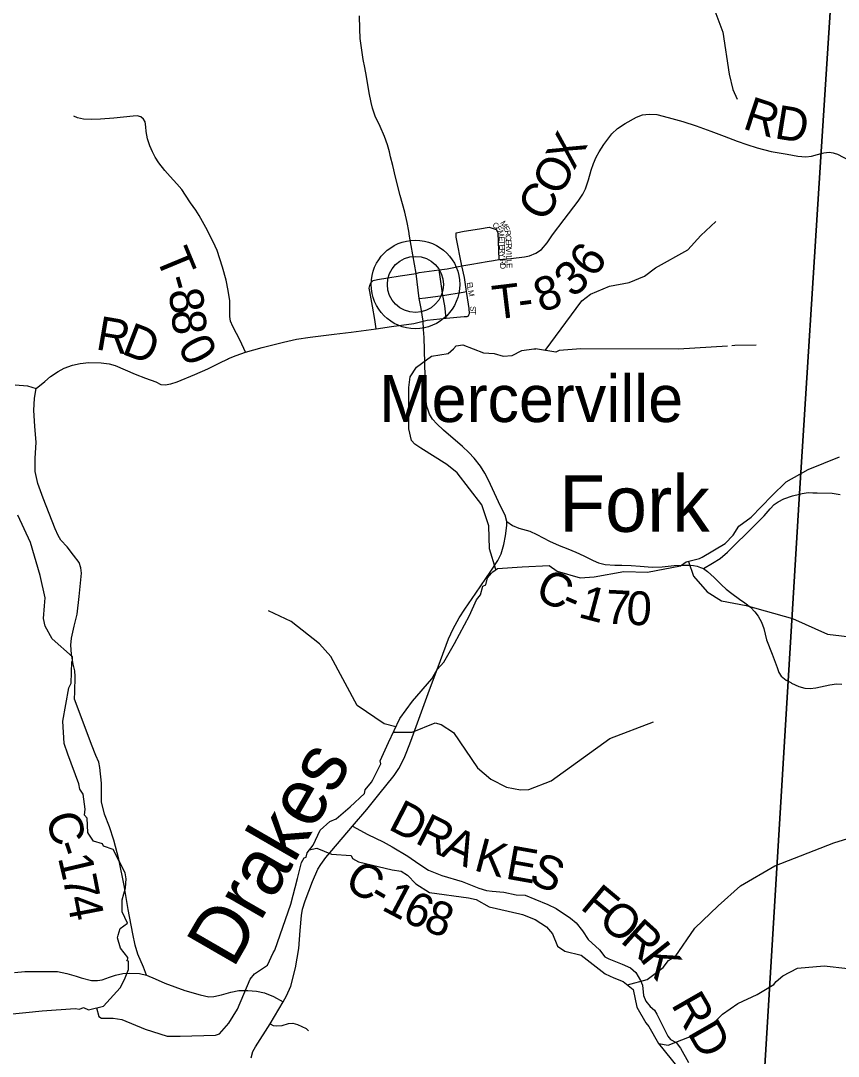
# Model space of a CAD drawing. Extents: x -1.8 to 75.7, y -2 to 25.
# Drawn here: x 4.882 to 6.256, y 15.242 to 16.983 of the extents above; entities that cross this region are included whole.
import ezdxf

# ---------------------------------------------------------------- set-up
doc = ezdxf.new("R2010")
doc.units = 0
for name, color, linetype in [('GM_X_County_Road', 7, 'Continuous'), ('GM_X_County_Road_Text', 7, 'Continuous'), ('GM_X_Minor_River', 7, 'Continuous'), ('GM_X_Minor_River_Text', 7, 'Continuous'), ('GM_X_State_Route', 7, 'Continuous'), ('GM_X_Township', 7, 'Continuous'), ('GM_X_Township_Road', 7, 'Continuous'), ('GM_X_Township_Road_Text', 7, 'Continuous'), ('GM_X_Township_Subdivision', 7, 'Continuous'), ('GM_X_Township_Subdivision_Text', 7, 'Continuous'), ('GM_X_Unincorporated', 7, 'Continuous'), ('GM_X_Unincorporated_Location', 7, 'Continuous'), ('GM_X_Unincorporated_Text', 7, 'Continuous')]:
    doc.layers.add(name, color=color, linetype=linetype)

msp = doc.modelspace()

# ---------------------------------------------------------------- linework, layer by layer
at = {"layer": 'GM_X_County_Road'}
for points in [[(5.2313, 16.415), (5.2438, 16.42), (5.2594, 16.4259), (5.2874, 16.4337), (5.3234, 16.4427), (5.3451, 16.4474), (5.3684, 16.4508), (5.4086, 16.4558), (5.4371, 16.4593), (5.479, 16.4652), (5.5047, 16.4687), (5.5422, 16.4737), (5.558, 16.4776)], [(4.8724, 16.3711), (4.8936, 16.369), (4.908, 16.3647), (4.9225, 16.3766), (4.9322, 16.3848), (4.9446, 16.3934), (4.9551, 16.3988), (4.9692, 16.4039), (4.9818, 16.4069), (4.9966, 16.4086), (5.0172, 16.4077), (5.0307, 16.406), (5.0407, 16.4032), (5.0574, 16.3962), (5.0741, 16.3889), (5.0915, 16.382), (5.1088, 16.3756), (5.1174, 16.3713), (5.1249, 16.3709), (5.1341, 16.3724), (5.1446, 16.3758), (5.1742, 16.388), (5.1964, 16.3979), (5.2166, 16.408), (5.2292, 16.4142), (5.2313, 16.415)], [(5.0934, 15.3788), (5.0881, 15.3921), (5.0786, 15.4141), (5.0742, 15.4291), (5.0705, 15.448), (5.0626, 15.4889), (5.0555, 15.5292), (5.0467, 15.5736), (5.0386, 15.6057), (5.0309, 15.6282), (5.0228, 15.649), (5.0177, 15.6697), (5.0175, 15.7014), (5.0151, 15.7276), (5.0131, 15.7368), (5.0082, 15.7478), (5.0006, 15.7661), (4.9819, 15.8171), (4.9724, 15.8426), (4.9728, 15.855), (4.9733, 15.8807), (4.9731, 15.8904), (4.9698, 15.9014), (4.9671, 15.9179), (4.9662, 15.933), (4.9673, 15.9451), (4.9717, 15.9652), (4.977, 15.9854), (4.9799, 16.0151), (4.9838, 16.0543), (4.9832, 16.0633), (4.9799, 16.0723), (4.9709, 16.0848), (4.9601, 16.0983), (4.9491, 16.1099), (4.9447, 16.1178), (4.9401, 16.1286), (4.9198, 16.1803), (4.9108, 16.2049), (4.9064, 16.225), (4.9064, 16.2478), (4.9079, 16.2738), (4.9057, 16.3013), (4.9038, 16.3275), (4.9049, 16.3482), (4.908, 16.3647)], [(5.6988, 16.1413), (5.7084, 16.1346), (5.7189, 16.1301), (5.7372, 16.1247), (5.7489, 16.1193), (5.7706, 16.1078), (5.7864, 16.1006), (5.8009, 16.0951), (5.8146, 16.0895), (5.8279, 16.0836), (5.8435, 16.0755), (5.8526, 16.0718), (5.8637, 16.0691), (5.8802, 16.068), (5.8921, 16.068), (5.9073, 16.0673), (5.9229, 16.0658), (5.943, 16.0646), (5.9594, 16.0651), (5.98, 16.0669), (5.9943, 16.0678), (6.0042, 16.0678), (6.0123, 16.0669), (6.0184, 16.0658), (6.024, 16.064), (6.029, 16.0622), (6.0358, 16.0569), (6.0471, 16.0468), (6.0593, 16.0348), (6.067, 16.0276), (6.0767, 16.0201), (6.0893, 16.0106), (6.0986, 16.0046), (6.1079, 15.9973), (6.1155, 15.9894), (6.121, 15.9822), (6.1268, 15.972), (6.1307, 15.9614), (6.1352, 15.9424), (6.1443, 15.9183), (6.1526, 15.8956), (6.1558, 15.8871), (6.1598, 15.8814), (6.1679, 15.8747), (6.1712, 15.8728), (6.1756, 15.8703)], [(6.1756, 15.8703), (6.1772, 15.8694), (6.189, 15.8638), (6.1994, 15.8609), (6.2084, 15.8606), (6.2179, 15.8618), (6.2416, 15.8668), (6.2525, 15.8683), (6.2615, 15.8676)], [(5.4393, 15.6292), (5.4649, 15.615), (5.4908, 15.6025), (5.5059, 15.5945), (5.5323, 15.5784), (5.5509, 15.5659), (5.5671, 15.5553), (5.5893, 15.5463), (5.6236, 15.5361), (5.6517, 15.5249), (5.6643, 15.5209), (5.6743, 15.5199), (5.6939, 15.518), (5.7144, 15.5139), (5.7292, 15.5131), (5.7459, 15.5063), (5.7673, 15.4972), (5.7814, 15.4905), (5.8059, 15.4742), (5.8154, 15.4668), (5.826, 15.4529), (5.8351, 15.4387), (5.8543, 15.421), (5.8633, 15.4097), (5.8702, 15.406), (5.8926, 15.3971), (5.9063, 15.3907), (5.9152, 15.3831), (5.9232, 15.3698), (5.9266, 15.3618), (5.9285, 15.3443), (5.9321, 15.3347), (5.9393, 15.3261), (5.9467, 15.3197), (5.9507, 15.3132), (5.9629, 15.2883), (5.9693, 15.276), (5.9737, 15.2707), (5.983, 15.2654), (5.9902, 15.2557), (6.0037, 15.232)], [(4.8716, 15.3832), (4.8889, 15.3845), (4.9276, 15.3845), (4.9437, 15.3845), (4.9595, 15.3812), (4.975, 15.3768), (4.9835, 15.3742), (5.0008, 15.3694), (5.0108, 15.3694), (5.0189, 15.3705), (5.0312, 15.3751), (5.041, 15.3786), (5.0534, 15.3814), (5.065, 15.3821), (5.0814, 15.3812), (5.0934, 15.3788), (5.1079, 15.3727), (5.1238, 15.3653), (5.1577, 15.353), (5.1837, 15.3454), (5.1979, 15.3421), (5.2064, 15.3425), (5.2193, 15.3456), (5.2348, 15.3502), (5.2486, 15.3526), (5.2633, 15.3528), (5.2783, 15.3515), (5.2914, 15.3489), (5.3067, 15.343), (5.3229, 15.334)]]:
    msp.add_lwpolyline(points, dxfattribs=at)
at = {"layer": 'GM_X_Minor_River'}
for points in [[(5.9283, 17.1384), (5.9903, 17.1035), (6.0164, 17.0554), (6.0416, 17.0172), (6.0617, 16.9637), (6.072, 16.8928), (6.0782, 16.867), (6.0859, 16.8507)], [(5.7632, 16.4287), (5.8245, 16.5122), (5.8392, 16.5232), (5.8713, 16.5365), (5.9044, 16.5431), (5.9297, 16.5537), (5.9482, 16.5675), (6.0025, 16.598), (6.0247, 16.6216), (6.0496, 16.6455)], [(5.6804, 16.0603), (5.6693, 16.095), (5.6686, 16.1341), (5.6564, 16.169), (5.615, 16.2228), (5.598, 16.237), (5.5542, 16.2642), (5.5439, 16.271), (5.5384, 16.2772), (5.5341, 16.2971), (5.5343, 16.3662), (5.536, 16.384), (5.547, 16.4003), (5.5722, 16.4189), (5.5999, 16.4237), (5.6088, 16.4314), (5.6135, 16.4362), (5.6249, 16.4381), (5.6593, 16.4245), (5.6774, 16.4235), (5.6927, 16.4189), (5.7079, 16.4199), (5.7237, 16.4285), (5.7442, 16.4316), (5.7472, 16.4315)], [(6.0696, 16.436), (5.9872, 16.4307), (5.8232, 16.4314), (5.7864, 16.4288), (5.781, 16.4255), (5.7468, 16.4315)], [(6.1176, 16.4376), (6.0819, 16.4368), (6.0769, 16.4365)], [(5.0095, 15.3237), (5.0131, 15.3092), (5.0176, 15.3065), (5.0373, 15.3062), (5.052, 15.304), (5.091, 15.2881), (5.128, 15.276), (5.1499, 15.2761), (5.2093, 15.2777), (5.2157, 15.28), (5.2316, 15.2979), (5.2463, 15.3215), (5.2674, 15.3721), (5.275, 15.3809), (5.2965, 15.3954), (5.3063, 15.4163), (5.309, 15.4205), (5.3357, 15.4981), (5.347, 15.541), (5.3538, 15.568), (5.358, 15.5757), (5.3617, 15.5768), (5.3632, 15.584), (5.3731, 15.5973), (5.3848, 15.6225), (5.4014, 15.6369), (5.412, 15.6411), (5.4354, 15.6617), (5.4595, 15.6842), (5.4607, 15.6899), (5.4712, 15.7028), (5.4735, 15.7067), (5.4867, 15.7337), (5.486, 15.739), (5.4999, 15.7694), (5.5188, 15.8101), (5.5403, 15.8394), (5.5724, 15.8768), (5.5818, 15.8924), (5.5928, 15.9049), (5.6105, 15.9361), (5.6362, 15.9829), (5.6479, 16.0096), (5.6543, 16.0176), (5.6584, 16.0324), (5.6634, 16.0347), (5.6664, 16.0465), (5.6728, 16.0541), (5.6751, 16.0564), (5.683, 16.0621), (5.7246, 16.0652), (5.7699, 16.0669), (5.7835, 16.0574), (5.8221, 16.0465), (5.8456, 16.048), (5.8951, 16.0569), (5.9351, 16.0562), (5.9907, 16.0666), (6.0001, 16.0731), (6.0224, 16.0792), (6.027, 16.0811), (6.0655, 16.1044), (6.0787, 16.1181), (6.0885, 16.133), (6.1089, 16.1482), (6.1441, 16.184), (6.1679, 16.2076), (6.2049, 16.2283), (6.2578, 16.25)], [(4.9612, 15.7503), (4.9552, 15.7682), (4.9525, 15.8058), (4.963, 15.8617), (4.9668, 15.8693), (4.9679, 15.905), (4.969, 15.9073), (4.9687, 15.9138), (4.935, 15.9437), (4.9229, 15.965), (4.9202, 15.9779), (4.9221, 15.9992), (4.9228, 16.0128), (4.9149, 16.0501), (4.8985, 16.1059), (4.8773, 16.1515)], [(6.0038, 16.0741), (6.0123, 16.0492), (6.0352, 16.0227), (6.0596, 16.0077), (6.1006, 15.9999), (6.1786, 15.9783), (6.2372, 15.9516), (6.3078, 15.9436), (6.3416, 15.9354), (6.3546, 15.9287), (6.3676, 15.9132), (6.3894, 15.8859), (6.4197, 15.836), (6.4433, 15.8194), (6.457, 15.8141), (6.5031, 15.7817), (6.5138, 15.7765), (6.5369, 15.772), (6.5521, 15.7706), (6.6135, 15.7853)], [(5.5121, 15.7958), (5.4927, 15.8013), (5.447, 15.8318), (5.4028, 15.9143), (5.3837, 15.9355), (5.3365, 15.9732), (5.2984, 15.9909)], [(5.5082, 15.7873), (5.5399, 15.7871), (5.5785, 15.8025), (5.5884, 15.8002), (5.6093, 15.7867), (5.6495, 15.7273), (5.672, 15.708), (5.6979, 15.6945), (5.7219, 15.69), (5.7355, 15.6909), (5.773, 15.7055), (5.8716, 15.7766), (5.9451, 15.8043)], [(4.8573, 15.3123), (4.9178, 15.3185), (4.9734, 15.3228), (4.9805, 15.3213), (4.9877, 15.3243), (4.996, 15.3206), (5.021, 15.3263), (5.0489, 15.3572), (5.0561, 15.3716), (5.0629, 15.3884), (5.0633, 15.402), (5.0602, 15.4028), (5.0621, 15.4062), (5.0617, 15.4081), (5.0496, 15.4241), (5.0447, 15.4411), (5.0458, 15.4457), (5.0492, 15.4571), (5.0613, 15.4659), (5.0526, 15.4853), (5.0522, 15.5054), (5.0582, 15.5255), (5.059, 15.5408), (5.0574, 15.5506), (5.0374, 15.5897), (5.0211, 15.5954), (5.0192, 15.5996), (5.0045, 15.6037), (4.9965, 15.6155), (4.9946, 15.6185), (4.9935, 15.6425), (4.9893, 15.6474), (4.9901, 15.6577), (4.987, 15.6831), (4.981, 15.6911), (4.9798, 15.7002), (4.9612, 15.7503)], [(5.9012, 15.3623), (5.9344, 15.3711), (5.9613, 15.3913), (5.9703, 15.4031), (5.9813, 15.4093), (6.0147, 15.4577), (6.054, 15.4954), (6.0914, 15.529), (6.1488, 15.5624), (6.248, 15.6008), (6.2863, 15.6128), (6.3219, 15.6183)], [(5.3665, 15.5892), (5.3796, 15.592), (5.4039, 15.5821), (5.4371, 15.5795), (5.4396, 15.5749), (5.4493, 15.5693), (5.5062, 15.5557)], [(5.5062, 15.5557), (5.5213, 15.5533), (5.5317, 15.5469), (5.5457, 15.5324), (5.5686, 15.5176), (5.6341, 15.5087), (5.6473, 15.506), (5.6688, 15.4932), (5.7203, 15.4816), (5.7248, 15.4804), (5.7464, 15.4724), (5.7653, 15.4601), (5.7756, 15.448), (5.7836, 15.4276), (5.7959, 15.4192), (5.8236, 15.4123), (5.8639, 15.3806), (5.8784, 15.3741), (5.8941, 15.3679), (5.9107, 15.3548), (5.917, 15.325), (5.9324, 15.2983), (5.9375, 15.2924), (5.9533, 15.2638), (5.9868, 15.2229)], [(5.9536, 15.2635), (5.9698, 15.261), (6.0257, 15.2828), (6.0512, 15.3029), (6.061, 15.3132), (6.0869, 15.331), (6.1195, 15.3462), (6.1472, 15.3628), (6.1511, 15.368), (6.1624, 15.3775), (6.1873, 15.3904), (6.2317, 15.3943), (6.2716, 15.3896)]]:
    msp.add_lwpolyline(points, dxfattribs=at)
at = {"layer": 'GM_X_State_Route'}
for points in [[(5.6916, 16.16), (5.6847, 16.1741), (5.6677, 16.2105), (5.6617, 16.2223), (5.6542, 16.2343), (5.6436, 16.2478), (5.6351, 16.2569), (5.6242, 16.2673), (5.5923, 16.2946), (5.5811, 16.3054), (5.574, 16.3134), (5.5687, 16.3217), (5.5664, 16.3283), (5.5644, 16.3346), (5.5634, 16.3434), (5.5621, 16.3579), (5.5612, 16.384), (5.5605, 16.4294), (5.5596, 16.4505), (5.5589, 16.4638), (5.558, 16.4776), (5.5548, 16.4992), (5.5516, 16.5157), (5.5463, 16.5577), (5.5354, 16.6205), (5.5339, 16.629), (5.5311, 16.6436), (5.5271, 16.6612), (5.5196, 16.6893), (5.5117, 16.72), (5.507, 16.7396), (5.5033, 16.7539), (5.5013, 16.7627), (5.4979, 16.7742), (5.4932, 16.7884), (5.4859, 16.8051), (5.4776, 16.8223), (5.4728, 16.8357), (5.4706, 16.8454), (5.4674, 16.8614), (5.4629, 16.8892), (5.46, 16.9041), (5.4575, 16.9176), (5.4543, 16.9375), (5.4525, 16.9531), (5.4516, 16.9694), (5.4509, 16.9913)], [(5.6824, 16.0738), (5.6835, 16.0756), (5.689, 16.0869), (5.6937, 16.1022), (5.6966, 16.1168), (5.6988, 16.1342), (5.6988, 16.1413), (5.6957, 16.1518), (5.6916, 16.16)], [(5.2692, 15.2398), (5.272, 15.2503), (5.2764, 15.2581), (5.3008, 15.2969), (5.3229, 15.334), (5.3286, 15.3438), (5.3355, 15.3599), (5.3438, 15.391), (5.3491, 15.4235), (5.3516, 15.4539), (5.3535, 15.4789), (5.3554, 15.4896), (5.3596, 15.5033), (5.3721, 15.5359), (5.381, 15.5566), (5.3859, 15.5648), (5.3947, 15.5763), (5.4047, 15.5881), (5.4393, 15.6292), (5.4632, 15.6573), (5.4837, 15.6821), (5.5093, 15.714), (5.5173, 15.7261), (5.5261, 15.7433), (5.5308, 15.7543), (5.5373, 15.7717), (5.5666, 15.8523), (5.5873, 15.9074), (5.6008, 15.944), (5.6087, 15.9608), (5.6188, 15.9792), (5.6282, 15.9936), (5.6466, 16.0204), (5.6716, 16.0574), (5.6824, 16.0738)]]:
    msp.add_lwpolyline(points, dxfattribs=at)
at = {"layer": 'GM_X_Township'}
for points in [[(6.0631, 14.1), (6.0891, 14.525), (6.1136, 14.9242), (6.1259, 15.1242), (6.1707, 15.8638), (6.1898, 16.179), (6.2265, 16.7539), (6.252, 17.1543), (5.4813, 17.1939), (5.2191, 17.2074), (4.6712, 17.2345), (4.4195, 17.2469), (3.6863, 17.2831), (3.1354, 17.3103), (2.1, 17.3659)], [(8.9, 17.0276), (8.8908, 17.028), (8.4894, 17.0481), (7.3049, 17.1072), (7.1962, 17.1121), (6.252, 17.1543), (6.2265, 16.7539), (6.1898, 16.179), (6.1707, 15.8638), (6.1259, 15.1242), (6.1136, 14.9242), (6.0891, 14.525), (6.0631, 14.1)]]:
    msp.add_lwpolyline(points, dxfattribs=at)
at = {"layer": 'GM_X_Township_Road'}
for points in [[(5.2333, 16.4928), (5.2333, 16.497), (5.2333, 16.512), (5.2307, 16.5292), (5.2273, 16.5469), (5.2211, 16.5684), (5.2121, 16.5964), (5.2054, 16.6112), (5.1928, 16.6354), (5.1817, 16.6555), (5.1761, 16.6645), (5.1673, 16.6769), (5.1589, 16.6896), (5.1525, 16.699), (5.1442, 16.7086), (5.1328, 16.7208), (5.1238, 16.7313), (5.114, 16.7442), (5.1078, 16.7534), (5.1031, 16.7622), (5.0988, 16.7725), (5.0949, 16.7844), (5.0928, 16.7964), (5.0921, 16.8044), (5.0911, 16.8127), (5.0883, 16.8176), (5.0836, 16.8215), (5.0776, 16.823), (5.0707, 16.8226), (5.0384, 16.8191), (5.0159, 16.8176), (5.0009, 16.817), (4.9876, 16.8172), (4.9773, 16.8194), (4.9711, 16.8226)], [(5.5851, 16.5642), (5.5986, 16.566), (5.6229, 16.5706), (5.6399, 16.5736), (5.6659, 16.5781), (5.6764, 16.5798), (5.6854, 16.5813), (5.7053, 16.5833), (5.7284, 16.5857), (5.737, 16.5876), (5.7475, 16.5923), (5.7567, 16.5985), (5.7665, 16.6094), (5.7754, 16.6231), (5.7948, 16.6486), (5.8185, 16.6794), (5.8262, 16.6911), (5.8307, 16.7004), (5.8356, 16.7153), (5.8401, 16.7316), (5.8444, 16.7429), (5.8485, 16.7534), (5.8536, 16.7624), (5.8617, 16.775), (5.8752, 16.7926), (5.8844, 16.8014), (5.8973, 16.8103), (5.9163, 16.8208), (5.9268, 16.8247), (5.9377, 16.8257), (5.9505, 16.8251), (5.97, 16.8204), (5.9942, 16.8135), (6.0169, 16.8061), (6.0415, 16.7971), (6.0637, 16.7885), (6.0858, 16.7802), (6.1018, 16.7746), (6.1192, 16.7693), (6.1429, 16.763), (6.1694, 16.7583), (6.1874, 16.7551), (6.2011, 16.7543), (6.2105, 16.7551), (6.2206, 16.7577), (6.2268, 16.7594), (6.2315, 16.7607), (6.2401, 16.7618), (6.2469, 16.7609), (6.2485, 16.7604)], [(6.2485, 16.7604), (6.2544, 16.7588), (6.273, 16.7483), (6.2888, 16.7389), (6.3068, 16.7282), (6.3164, 16.7213), (6.3261, 16.7123), (6.3351, 16.7016), (6.3445, 16.6886), (6.3588, 16.664), (6.3652, 16.6539), (6.3732, 16.6464), (6.3813, 16.6424), (6.3875, 16.6396), (6.3882, 16.6395)], [(5.5463, 16.5577), (5.5514, 16.5595), (5.5851, 16.5642)], [(5.2594, 16.4259), (5.2504, 16.4454), (5.2384, 16.469), (5.2345, 16.4776), (5.2335, 16.4855), (5.2333, 16.4928)], [(6.029, 16.0622), (6.044, 16.0712), (6.0571, 16.0791), (6.0693, 16.0893), (6.0805, 16.101), (6.104, 16.1236), (6.1199, 16.1396), (6.1312, 16.1505), (6.1409, 16.1624), (6.1476, 16.1695), (6.1548, 16.1744), (6.1639, 16.179), (6.1784, 16.1841), (6.1903, 16.1871), (6.1951, 16.1884), (6.205, 16.1896), (6.2126, 16.1895)], [(6.2126, 16.1895), (6.2202, 16.1893), (6.2454, 16.1886), (6.2588, 16.1866)], [(5.3008, 15.2969), (5.3063, 15.294), (5.312, 15.2936), (5.3212, 15.2942), (5.3317, 15.2973), (5.3391, 15.2979), (5.347, 15.2958), (5.3614, 15.289), (5.3653, 15.2851)]]:
    msp.add_lwpolyline(points, dxfattribs=at)
at = {"layer": 'GM_X_Township_Subdivision'}
for points in [[(5.6229, 16.5706), (5.6136, 16.619), (5.6138, 16.6264), (5.6268, 16.6293), (5.6527, 16.6333)], [(5.6527, 16.6333), (5.6691, 16.6358), (5.6805, 16.6319), (5.6836, 16.6264), (5.6854, 16.5813)], [(5.634, 16.487), (5.6351, 16.4886), (5.636, 16.4905), (5.6356, 16.4994), (5.6315, 16.5244), (5.631, 16.5277), (5.6273, 16.5513), (5.6229, 16.5706)], [(5.4739, 16.5461), (5.474, 16.5462), (5.4811, 16.5481), (5.4986, 16.5508), (5.5195, 16.5538), (5.5463, 16.5577)], [(5.5966, 16.4829), (5.5943, 16.5036), (5.5911, 16.5208), (5.5851, 16.5642)], [(5.479, 16.4652), (5.4767, 16.4808), (5.4728, 16.5029), (5.4706, 16.5153), (5.4685, 16.5276), (5.4676, 16.5332), (5.4683, 16.538), (5.4703, 16.5424), (5.4739, 16.5461)], [(5.5516, 16.5157), (5.5623, 16.5171), (5.5911, 16.5208), (5.6255, 16.5267), (5.631, 16.5277)], [(5.558, 16.4776), (5.5647, 16.4795), (5.5966, 16.4829), (5.6268, 16.4856), (5.6323, 16.4859), (5.634, 16.487)]]:
    msp.add_lwpolyline(points, dxfattribs=at)
at = {"layer": 'GM_X_Unincorporated'}
for radius in [0.0744, 0.0472]:
    msp.add_circle((5.5451, 16.5396), radius, dxfattribs=at)
at = {"layer": 'GM_X_Unincorporated_Location'}
msp.add_line((5.5451, 16.5396), (5.5451, 16.5396), dxfattribs=at)

# ---------------------------------------------------------------- texts
at = {"layer": 'GM_X_County_Road_Text'}
for s, height, rotation, p in [('R', 0.0568, 350.3214, (5.0064, 16.4308)), ('D', 0.0568, 338.9366, (5.0495, 16.4237)), ('C', 0.0568, 336.0016, (5.7435, 16.0123)), ('1', 0.0568, 345.0845, (5.8168, 15.9808)), ('-', 0.0568, 336.7539, (5.7868, 15.993)), ('7', 0.0568, 357.1207, (5.8635, 15.9698)), ('0', 0.0568, 356.7979, (5.8984, 15.9681)), ('D', 0.0568, 332.6448, (5.4973, 15.625)), ('C', 0.0568, 285.9744, (4.9234, 15.6447)), ('R', 0.0568, 333.3021, (5.5424, 15.6017)), ('A', 0.0568, 335.2103, (5.5859, 15.5799)), ('-', 0.0568, 288.6765, (4.9371, 15.597)), ('K', 0.0568, 345.0795, (5.6413, 15.5553)), ('E', 0.0568, 349.8639, (5.6947, 15.5413)), ('1', 0.0568, 283.2417, (4.9442, 15.5763)), ('S', 0.0568, 337.7336, (5.7335, 15.5347)), ('C', 0.0568, 328.6259, (5.4229, 15.5275)), ('7', 0.0568, 281.139, (4.9521, 15.5427)), ('1', 0.0568, 332.1583, (5.4862, 15.4895)), ('F', 0.0568, 320.2334, (5.8201, 15.4916)), ('4', 0.0568, 280.916, (4.9588, 15.5085)), ('-', 0.0568, 329.6337, (5.4636, 15.5026)), ('6', 0.0568, 335.1745, (5.52, 15.4717)), ('8', 0.0568, 339.4981, (5.5561, 15.4552)), ('O', 0.0568, 320.2299, (5.8496, 15.467)), ('R', 0.0568, 318.0746, (5.8876, 15.4354)), ('K', 0.0568, 308.2394, (5.9206, 15.4061)), ('RD', 0.05682, 299.8686, (5.9738, 15.3294))]:
    msp.add_text(s, height=height, rotation=rotation, dxfattribs=at).set_placement(p)
at = {"layer": 'GM_X_Minor_River_Text'}
for s, height, rotation, p in [('Fork', 0.0947, 359.9962, (5.7864, 16.1238)), ('Drakes', 0.09469, 59.9948, (5.2386, 15.388))]:
    msp.add_text(s, height=height, rotation=rotation, dxfattribs=at).set_placement(p)
at = {"layer": 'GM_X_Township_Road_Text'}
for s, rotation, p in [('R', 341.8292, (6.093, 16.8023)), ('D', 350.8483, (6.1467, 16.7855)), ('X', 62.0664, (5.8117, 16.7304)), ('O', 62.6275, (5.7888, 16.6861)), ('C', 57.9501, (5.7615, 16.6421)), ('T', 292.5216, (5.1079, 16.5868)), ('6', 53.6809, (5.8447, 16.5484)), ('3', 41.9178, (5.8101, 16.5156)), ('-', 285.7953, (5.1236, 16.5492)), ('8', 19.4828, (5.7564, 16.4916)), ('T', 6.8885, (5.6778, 16.4804)), ('8', 279.6839, (5.1296, 16.5284)), ('-', 7.4441, (5.7206, 16.4856)), ('8', 274.0676, (5.1353, 16.4953)), ('0', 297.5303, (5.1446, 16.4362))]:
    msp.add_text(s, height=0.0568, rotation=rotation, dxfattribs=at).set_placement(p)
at = {"layer": 'GM_X_Township_Subdivision_Text'}
for s, rotation, p in [('C', 328.8363, (5.6736, 16.637)), ('M', 300.2532, (5.687, 16.6431)), ('E', 307.6402, (5.6793, 16.6337)), ('M', 283.6055, (5.6829, 16.6294)), ('E', 300.2397, (5.6921, 16.6345)), ('R', 281.0194, (5.6951, 16.6295)), ('E', 273.007, (5.6852, 16.6201)), ('T', 272.2682, (5.6855, 16.6135)), ('E', 272.2136, (5.6858, 16.6069)), ('C', 272.1863, (5.6965, 16.6225)), ('E', 272.2088, (5.6968, 16.615)), ('R', 272.2105, (5.697, 16.6084)), ('R', 272.1863, (5.6861, 16.6002)), ('Y', 272.2077, (5.6863, 16.5927)), ('V', 272.1862, (5.6973, 16.6009)), ('I', 272.2173, (5.6977, 16.5925)), ('L', 272.1863, (5.6978, 16.5884)), ('R', 272.2105, (5.6868, 16.5819)), ('D', 272.2081, (5.6871, 16.5744)), ('L', 272.2153, (5.6981, 16.5817)), ('E', 272.2136, (5.6983, 16.5751)), ('E', 278.2248, (5.6312, 16.5427)), ('L', 278.1977, (5.6321, 16.5361)), ('M', 281.6945, (5.6332, 16.5289)), ('S', 272.9791, (5.637, 16.5027)), ('T', 269.4262, (5.6374, 16.4962))]:
    msp.add_text(s, height=0.00947, rotation=rotation, dxfattribs=at).set_placement(p)
at = {"layer": 'GM_X_Unincorporated_Text'}
msp.add_text('Mercerville', height=0.078977, rotation=0, dxfattribs=at).set_placement((5.4844, 16.3083))

doc.saveas('drawing.dxf')
